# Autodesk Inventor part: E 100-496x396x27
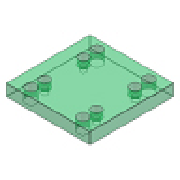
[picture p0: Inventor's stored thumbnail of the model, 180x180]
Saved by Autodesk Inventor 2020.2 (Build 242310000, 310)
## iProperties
Manager: www.cadconsulting.pl
Company: Fabian Stasiak CAD Consulting
IsCustomPart: 1
Created: 2014-02
Part Number: E 100-496x396x27
Material: S 55 C
Description: Top Clamping Plate
Document SubType Name: Modeling
Designer: F.Stasiak
Standard Revision: 1
Manufacturer: DME
Language: pl-PL
Size Designation: 496x396x27
Categories: <MemberInstance><Categories><Category DisplayName="Forma wtryskowa" InternalName="349578f2-f4d4-4954-8c09-8e99297a61c0" Mnemonic="MOLD"><Category DisplayName="P
Density: 7.85 g/cm^3
Appearance: Clear - Green 1
Catalog Web Link: www.expertbooks.pl
Author: F.Stasiak
Subject: Zbiór ćwiczeń. Autodesk Inventor 2020. Kurs Professional
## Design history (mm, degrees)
sketch "Sketch1"
  geometry: L1 (-198, 248)-(198, 248); L2 (198, 248)-(198, -248); L3 (198, -248)-(-198, -248); L4 (-198, -248)-(-198, 248); 3 further points
  constraints: 8 end point, 2 midpoint, 2 parallel, 1 horizontal, 1 horizontal alignment, 1 perpendicular, 1 vertical alignment
  dimensions: "d102" = 396 distance between parallel lines of L2 L4 (= W_); "d103" = 496 distance between parallel lines of L3 L1 (= L)
extrude "Extrusion1" new body sketch "Sketch1" distance "d20" = 27 (= H_); taper "d30" = 0 deg
sketch "Sketch2"
  geometry: 3 further points
  dimensions: "d72" = 137 horizontal distance of point (0, 0) point (-137, 165) (= 0.5 x S1_W); "d73" = 137 horizontal distance of point (0, 0) point (-137, 208) (= 0.5 x GP_W); "d74" = 208 vertical distance of point (0, 0) point (-137, 208) (= 0.5 x GP_L); "d75" = 165 vertical distance of point (0, 0) point (-137, 165) (= 0.5 x S1_L)
hole "Hole1" sketch "Sketch2" diameter "d76" = 42 (= GP_d1); stored, may be unused: countersink angle "d80" = 90 deg, drill point angle "d82" = 0 deg; dims "d77" = 6, "d78" = 4, "d79" = 2, "d81" = 27 (= H_)
pattern_linear "Rectangular Pattern1" dims "d98" = 416 (computed from GP_L, Nl), "d101" = 274 (computed from GP_W, Nw)
hole "Hole2" sketch "Sketch2" diameter "d83" = 18 (= S1_d1); stored, may be unused: countersink angle "d87" = 90 deg, drill point angle "d89" = 0 deg; dims "d84" = 6, "d85" = 26 (= S1_d2), "d86" = 21 (= S1_k), "d88" = 27 (= H_)
pattern_linear "Rectangular Pattern2" dims "d92" = 330 (computed from S1_L, Ns), "d95" = 274 (computed from S1_W, Nw)
chamfer "Chamfer1" distance "d104" = 0.5; stored, may be unused: second distance "d105" = 2, angle "d106" = 45 deg
node "Płaszczyzna konstrukcyjna2"
node "Płaszczyzna konstrukcyjna3"
node "Płaszczyzna konstrukcyjna4"
node "Płaszczyzna konstrukcyjna5"
feature "Rzeźbienie1"
body "Solid1"
feature "Powierzchnia1"
body "Srf1"
other parameters: "L" = 496 [user parameter; used in 1 equation term], "W_" = 396 [user parameter; used in 1 equation term], "H_" = 27 [user parameter; used in 3 equation terms], "S1_W" = 274 [user parameter; used in 2 equation terms], "S1_d1" = 18 [user parameter; used in 1 equation term], "S1_d2" = 26 [user parameter; used in 1 equation term], "S1_k" = 21 [user parameter; used in 1 equation term], "GP_d1" = 42 [user parameter; used in 1 equation term], "GP_W" = 274 [user parameter; used in 2 equation terms], "GP_L" = 416 [user parameter; used in 2 equation terms]
